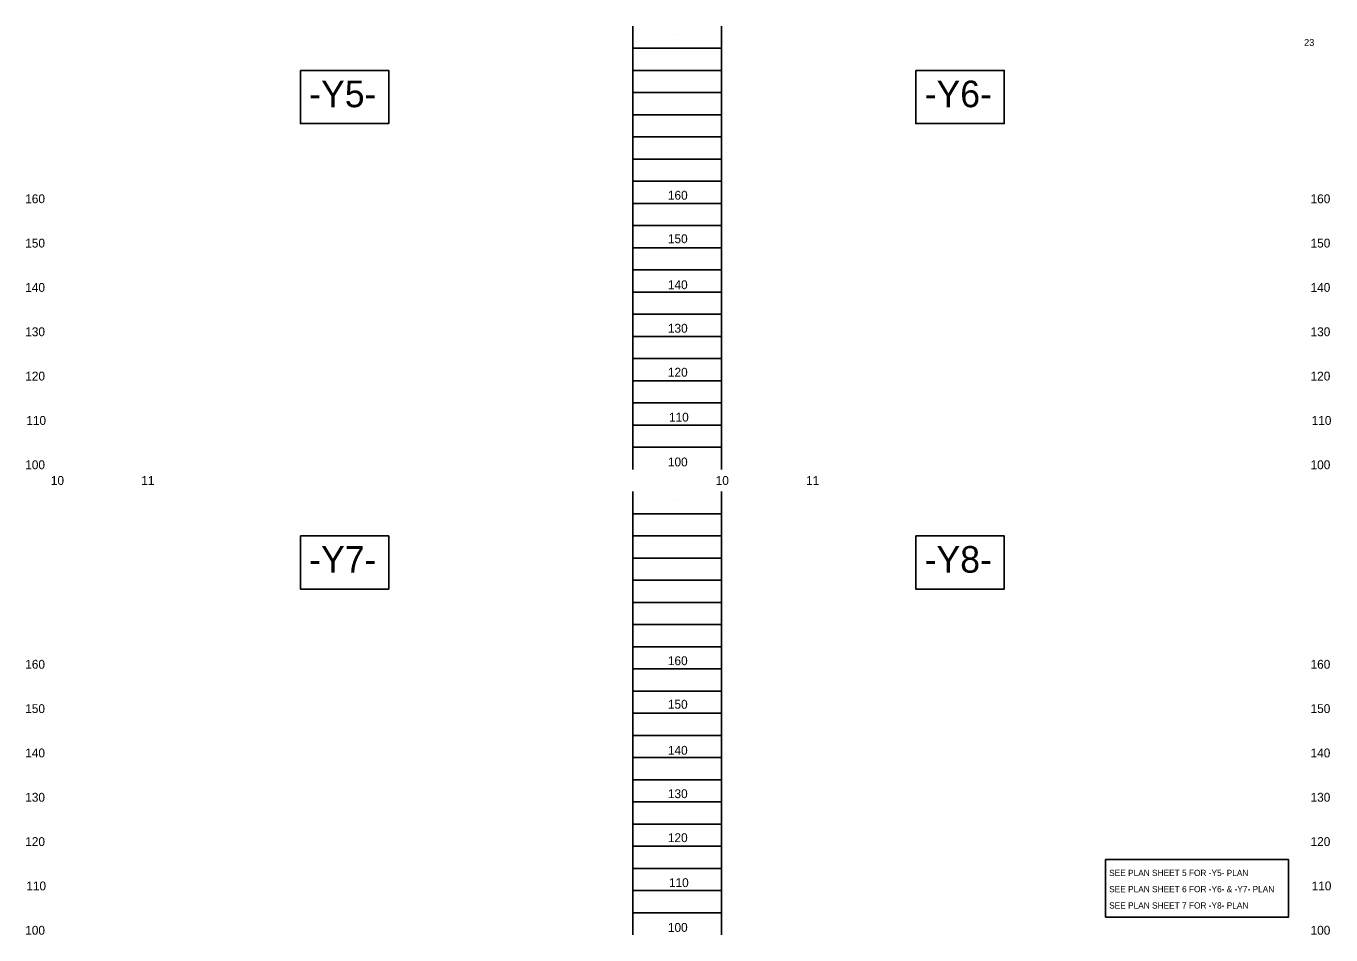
# Model space of a CAD drawing. Extents: x 2364289 to 2366249, y 588759 to 610062.
# Drawn here: x 2364469 to 2365941, y 596251 to 597276 of the extents above; entities that cross this region are included whole.
import ezdxf

# ---------------------------------------------------------------- set-up
doc = ezdxf.new("R2010")
doc.units = 0
for name, color, linetype in [('Exist Vertical Profile Horizontal Axis Label Major', 7, 'Continuous'), ('Exist Vertical Profile Vertical Axis Label', 7, 'Continuous'), ('Prop DSN Text', 7, 'Continuous'), ('Prop Grid Mask', 7, 'Continuous'), ('Sheet Data Field CELL', 7, 'Continuous'), ('Sheet DOT Grid CELL', 7, 'Continuous'), ('Sheet Profile CELL', 7, 'Continuous'), ('Sheet Profile Grid Major CELL', 7, 'Continuous'), ('Sheet Profile Grid Middle CELL', 7, 'Continuous'), ('Sheet Profile Grid Minor CELL', 7, 'Continuous')]:
    doc.layers.add(name, color=color, linetype=linetype)

msp = doc.modelspace()

# ---------------------------------------------------------------- linework, layer by layer
at = {"layer": 'Prop Grid Mask'}
for points in [[(2364778.5, 597226.5), (2364878.2, 597226.5), (2364878.2, 597166.6), (2364778.5, 597166.6)], [(2365472.7, 597226.5), (2365572.4, 597226.5), (2365572.4, 597166.6), (2365472.7, 597166.6)], [(2364778.5, 596701.5), (2364878.2, 596701.5), (2364878.2, 596641.6), (2364778.5, 596641.6)], [(2365472.7, 596701.5), (2365572.4, 596701.5), (2365572.4, 596641.6), (2365472.7, 596641.6)], [(2365686.7, 596336.5), (2365893.3, 596336.5), (2365893.3, 596271.5), (2365686.7, 596271.5)]]:
    msp.add_lwpolyline(points, close=True, dxfattribs=at)
at = {"layer": 'Sheet DOT Grid CELL'}
msp.add_line((2365153.3, 596776.5), (2365153.3, 597276.5), dxfattribs=at)
at = {"layer": 'Sheet Profile CELL'}
for p, q in [((2365153.3, 597276.5), (2365153.3, 596776.5)), ((2365253.3, 597276.5), (2365253.3, 596776.5)), ((2365153.3, 596751.5), (2365153.3, 596251.5)), ((2365253.3, 596751.5), (2365253.3, 596251.5))]:
    msp.add_line(p, q, dxfattribs=at)
at = {"layer": 'Sheet Profile Grid Major CELL'}
for p, q in [((2365153.3, 597226.5), (2365253.3, 597226.5)), ((2365153.3, 597176.5), (2365253.3, 597176.5)), ((2365153.3, 597126.5), (2365253.3, 597126.5)), ((2365153.3, 597076.5), (2365253.3, 597076.5)), ((2365153.3, 597026.5), (2365253.3, 597026.5)), ((2365153.3, 596976.5), (2365253.3, 596976.5)), ((2365153.3, 596926.5), (2365253.3, 596926.5)), ((2365153.3, 596876.5), (2365253.3, 596876.5)), ((2365153.3, 596826.5), (2365253.3, 596826.5)), ((2365153.3, 596701.5), (2365253.3, 596701.5)), ((2365153.3, 596651.5), (2365253.3, 596651.5)), ((2365153.3, 596601.5), (2365253.3, 596601.5)), ((2365153.3, 596551.5), (2365253.3, 596551.5)), ((2365153.3, 596501.5), (2365253.3, 596501.5)), ((2365153.3, 596451.5), (2365253.3, 596451.5)), ((2365153.3, 596401.5), (2365253.3, 596401.5)), ((2365153.3, 596351.5), (2365253.3, 596351.5)), ((2365153.3, 596301.5), (2365253.3, 596301.5))]:
    msp.add_line(p, q, dxfattribs=at)
at = {"layer": 'Sheet Profile Grid Middle CELL'}
for p, q in [((2365153.3, 597251.5), (2365253.3, 597251.5)), ((2365153.3, 597201.5), (2365253.3, 597201.5)), ((2365153.3, 597151.5), (2365253.3, 597151.5)), ((2365153.3, 597101.5), (2365253.3, 597101.5)), ((2365153.3, 597051.5), (2365253.3, 597051.5)), ((2365153.3, 597001.5), (2365253.3, 597001.5)), ((2365153.3, 596951.5), (2365253.3, 596951.5)), ((2365153.3, 596901.5), (2365253.3, 596901.5)), ((2365153.3, 596851.5), (2365253.3, 596851.5)), ((2365153.3, 596801.5), (2365253.3, 596801.5)), ((2365153.3, 596726.5), (2365253.3, 596726.5)), ((2365153.3, 596676.5), (2365253.3, 596676.5)), ((2365153.3, 596626.5), (2365253.3, 596626.5)), ((2365153.3, 596576.5), (2365253.3, 596576.5)), ((2365153.3, 596526.5), (2365253.3, 596526.5)), ((2365153.3, 596476.5), (2365253.3, 596476.5)), ((2365153.3, 596426.5), (2365253.3, 596426.5)), ((2365153.3, 596376.5), (2365253.3, 596376.5)), ((2365153.3, 596326.5), (2365253.3, 596326.5)), ((2365153.3, 596276.5), (2365253.3, 596276.5))]:
    msp.add_line(p, q, dxfattribs=at)
at = {"layer": 'Sheet Profile Grid Minor CELL'}
for p, q in [((2365203.3, 597266.5), (2365203.3, 597266.5)), ((2365203.3, 597266.5), (2365203.3, 597266.5)), ((2365203.3, 596741.5), (2365203.3, 596741.5))]:
    msp.add_line(p, q, dxfattribs=at)

# ---------------------------------------------------------------- texts
at = {"layer": 'Exist Vertical Profile Horizontal Axis Label Major'}
for s, p in [('10', (2364496.9, 596759)), ('11', (2364598.9, 596759)), ('10', (2365246.9, 596759)), ('11', (2365348.9, 596759))]:
    msp.add_text(s, height=10, dxfattribs=at).set_placement(p)
at = {"layer": 'Exist Vertical Profile Vertical Axis Label'}
for s, p in [('160', (2365193, 597080.7)), ('160', (2364468, 597076.7)), ('160', (2365918, 597076.7)), ('150', (2364468, 597026.7)), ('150', (2365193, 597031.6)), ('150', (2365918, 597026.7)), ('140', (2364468, 596976.7)), ('140', (2365193, 596979.7)), ('140', (2365918, 596976.7)), ('130', (2364468, 596926.7)), ('130', (2365193, 596930.7)), ('130', (2365918, 596926.7)), ('120', (2364468, 596876.7)), ('120', (2365193, 596881.1)), ('120', (2365918, 596876.7)), ('110', (2365194.2, 596830.4)), ('110', (2364469.2, 596826.7)), ('110', (2365919.2, 596826.7)), ('100', (2364468, 596776.7)), ('100', (2365193, 596779.9)), ('100', (2365918, 596776.7)), ('160', (2364468, 596551.7)), ('160', (2365193, 596555.7)), ('160', (2365918, 596551.7)), ('150', (2365193, 596506.6)), ('150', (2364468, 596501.7)), ('150', (2365918, 596501.7)), ('140', (2364468, 596451.7)), ('140', (2365193, 596454.7)), ('140', (2365918, 596451.7)), ('130', (2364468, 596401.7)), ('130', (2365193, 596405.7)), ('130', (2365918, 596401.7)), ('120', (2364468, 596351.7)), ('120', (2365193, 596356.1)), ('120', (2365918, 596351.7)), ('110', (2364469.2, 596301.7)), ('110', (2365194.2, 596305.4)), ('110', (2365919.2, 596301.7)), ('100', (2365193, 596254.9)), ('100', (2364468, 596251.7)), ('100', (2365918, 596251.7))]:
    msp.add_text(s, height=10, dxfattribs=at).set_placement(p)
at = {"layer": 'Prop DSN Text'}
for s, p in [('SEE PLAN SHEET 5 FOR -Y5- PLAN', (2365690.8, 596317.9)), ('SEE PLAN SHEET 6 FOR -Y6- & -Y7- PLAN', (2365690.8, 596299.6)), ('SEE PLAN SHEET 7 FOR -Y8- PLAN', (2365690.8, 596281.2))]:
    msp.add_text(s, height=7, dxfattribs=at).set_placement(p)
at = {"layer": 'Prop Grid Mask'}
for s, p in [('-Y5-', (2364788.4, 597185)), ('-Y6-', (2365482.7, 597185)), ('-Y7-', (2364788.4, 596660)), ('-Y8-', (2365482.7, 596660))]:
    msp.add_text(s, height=30, dxfattribs=at).set_placement(p)
at = {"layer": 'Sheet Data Field CELL'}
msp.add_text('23', height=7.75, dxfattribs=at).set_placement((2365910.7, 597254.1))

doc.saveas('drawing.dxf')
